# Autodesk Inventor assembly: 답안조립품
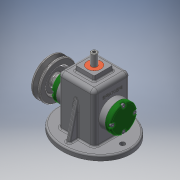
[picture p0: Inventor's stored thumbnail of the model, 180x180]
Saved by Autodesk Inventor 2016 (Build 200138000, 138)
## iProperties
Created: 2017-07
Part Number: 답안조립품
Material: 일반
Document SubType Name: Assembly
Designer: USER
Author: USER
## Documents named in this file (16)
- C:\Users\USER\Desktop\470707V1022\답안조립품.iam
- C:\Users\USER\Desktop\470707V1022\본체.ipt
- C:\Users\USER\Desktop\470707V1022\V벨트풀리.ipt
- C:\Users\USER\Desktop\470707V1022\고정핀 1.2 x  8.ipt
- C:\Users\USER\Desktop\470707V1022\뒤커버.ipt
- C:\Users\USER\Desktop\470707V1022\링크.ipt
- C:\Users\USER\Desktop\470707V1022\멈춤나사 M3x8.ipt
- C:\Users\USER\Desktop\470707V1022\베어링 12 x 32 x 10.ipt
- C:\Users\USER\Desktop\470707V1022\볼트 M4 x 12.ipt
- C:\Users\USER\Desktop\470707V1022\부시.ipt
- C:\Users\USER\Desktop\470707V1022\슬라이드.ipt
- C:\Users\USER\Desktop\470707V1022\앞커버.ipt
- C:\Users\USER\Desktop\470707V1022\오일실 12 25 7.ipt
- C:\Users\USER\Desktop\470707V1022\키 4 x 4 x 10.ipt
- C:\Users\USER\Desktop\470707V1022\편심축.ipt
- C:\Users\USER\Desktop\470707V1022\핀 5 x 18.ipt
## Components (3 placed, 3 different names)
1. V벨트풀리:1
2. 고정핀 1.2 x  8:1
3. 핀 5 x 18:1
